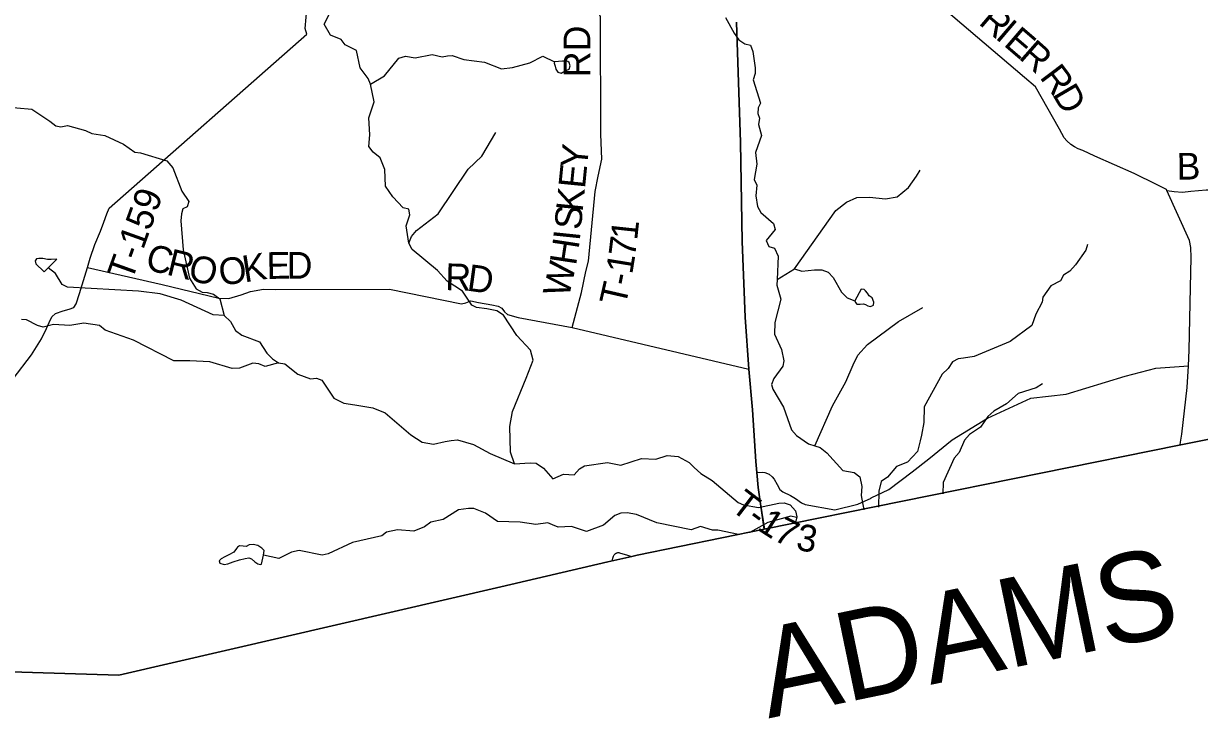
# Model space of a CAD drawing. Extents: x 1525783 to 1900577, y 218250 to 627376.
# Drawn here: x 1651566 to 1664775, y 372547 to 380350 of the extents above; entities that cross this region are included whole.
import ezdxf

# ---------------------------------------------------------------- set-up
doc = ezdxf.new("R2010")
doc.units = 0
for name, color, linetype in [('GM_X_Adjacent_County', 7, 'Continuous'), ('GM_X_Adjacent_County_Text', 7, 'Continuous'), ('GM_X_County', 7, 'Continuous'), ('GM_X_County_Road', 7, 'Continuous'), ('GM_X_Minor_Lake', 7, 'Continuous'), ('GM_X_Minor_River', 7, 'Continuous'), ('GM_X_State_Route', 7, 'Continuous'), ('GM_X_Township', 7, 'Continuous'), ('GM_X_Township_Road', 7, 'Continuous'), ('GM_X_Township_Road_Text', 7, 'Continuous'), ('GM_X_Township_ROW', 7, 'Continuous')]:
    doc.layers.add(name, color=color, linetype=linetype)

msp = doc.modelspace()

# ---------------------------------------------------------------- linework, layer by layer
at = {"layer": 'GM_X_Adjacent_County'}
msp.add_lwpolyline([(1639218, 373602), (1647962, 373191), (1648875, 373148), (1652636, 373033), (1656929, 374027), (1658129, 374305), (1658400, 374367), (1658458, 374381), (1659887, 374671), (1664545, 375615), (1665666, 375842), (1669148, 376597), (1674179, 377598), (1676204, 378017), (1679810, 378742), (1683755, 379513), (1684465, 379654), (1684870, 379728), (1687556, 380216)], dxfattribs=at)
at = {"layer": 'GM_X_County'}
msp.add_lwpolyline([(1687556, 380216), (1684870, 379728), (1684465, 379654), (1683755, 379513), (1679810, 378742), (1676204, 378017), (1674179, 377598), (1669148, 376597), (1665666, 375842), (1664545, 375615), (1659887, 374671), (1658458, 374381), (1658400, 374367), (1658129, 374305), (1656929, 374027), (1652636, 373033), (1648875, 373148), (1647962, 373191), (1639218, 373602)], dxfattribs=at)
at = {"layer": 'GM_X_County_Road'}
msp.add_lwpolyline([(1658176, 374315), (1658181, 374330), (1658186, 374347), (1658190, 374360), (1658194, 374370), (1658198, 374377), (1658201, 374383), (1658206, 374388), (1658209, 374392), (1658213, 374396), (1658218, 374400), (1658221, 374402), (1658226, 374404), (1658231, 374406), (1658236, 374408), (1658241, 374409), (1658247, 374410), (1658253, 374409), (1658261, 374408), (1658271, 374405), (1658287, 374400), (1658350, 374380), (1658394, 374366)], dxfattribs=at)
at = {"layer": 'GM_X_Minor_Lake'}
for points in [[(1657532, 379919), (1657528, 379905), (1657537, 379871), (1657547, 379837), (1657569, 379802), (1657607, 379794), (1657651, 379819), (1657694, 379837), (1657706, 379873), (1657696, 379913), (1657681, 379925), (1657646, 379926), (1657620, 379926)], [(1657620, 379926), (1657532, 379919)], [(1651940, 377704), (1651878, 377701), (1651837, 377699), (1651785, 377710), (1651737, 377713), (1651711, 377707), (1651697, 377685), (1651706, 377653), (1651732, 377627), (1651768, 377592), (1651800, 377560), (1651842, 377607)], [(1651842, 377607), (1651940, 377704)], [(1660904, 377238), (1660912, 377217), (1660928, 377197), (1660964, 377199), (1661000, 377204), (1661024, 377196), (1661050, 377180), (1661080, 377171), (1661114, 377187), (1661117, 377223), (1661097, 377269), (1661064, 377294), (1661046, 377322), (1661024, 377350), (1661008, 377363), (1660976, 377369)], [(1660976, 377369), (1660904, 377238)], [(1654263, 374382), (1654270, 374432), (1654242, 374461), (1654200, 374491), (1654146, 374500), (1654102, 374496), (1654068, 374479), (1654034, 374483), (1653994, 374484), (1653969, 374470), (1653959, 374456), (1653927, 374416), (1653874, 374383), (1653828, 374361), (1653787, 374340), (1653765, 374318), (1653771, 374290), (1653819, 374277), (1653863, 374285), (1653923, 374306), (1653994, 374327), (1654056, 374343), (1654098, 374350), (1654128, 374340), (1654166, 374305), (1654200, 374283), (1654224, 374276), (1654238, 374280)], [(1654238, 374280), (1654263, 374382)]]:
    msp.add_lwpolyline(points, dxfattribs=at)
at = {"layer": 'GM_X_Minor_River'}
for points in [[(1655894, 377882), (1655863, 378077), (1655904, 378201), (1655895, 378265), (1655831, 378282), (1655714, 378402), (1655631, 378523), (1655625, 378709), (1655573, 378840), (1655493, 378904), (1655444, 378968), (1655456, 379100), (1655444, 379291), (1655506, 379469), (1655462, 379670), (1655439, 379732), (1655346, 379851), (1655307, 380048), (1655181, 380112), (1655135, 380169), (1655016, 380220), (1654943, 380342), (1655013, 380481)], [(1659452, 380417), (1659548, 380241), (1659601, 380168), (1659667, 380123), (1659731, 380106), (1659760, 380036), (1659786, 379853), (1659785, 379787), (1659763, 379717), (1659844, 379456), (1659817, 379404), (1659814, 379338), (1659834, 379287), (1659823, 379217), (1659855, 379093), (1659789, 378903), (1659803, 378771), (1659775, 378598), (1659803, 378536), (1659793, 378416), (1659810, 378295), (1659849, 378229), (1659990, 378105), (1660009, 378036), (1659909, 377915), (1659937, 377845), (1660001, 377826), (1660044, 377739), (1660031, 377477), (1660028, 377411), (1660072, 377256), (1660007, 376992), (1660003, 376862), (1660081, 376690), (1660106, 376564), (1660095, 376502), (1659995, 376365), (1659968, 376295), (1659982, 376243), (1660102, 376041), (1660191, 375789), (1660250, 375726), (1660384, 375632), (1660453, 375607), (1660513, 375589), (1660589, 375530), (1660769, 375331), (1660897, 375309), (1660961, 375260), (1660984, 375152), (1660974, 375050), (1661005, 374888)], [(1655462, 379670), (1655620, 379762), (1655781, 379960), (1655857, 379982), (1655966, 379966), (1656155, 380000), (1656269, 379976), (1656329, 379986), (1656381, 379989), (1656511, 379947), (1656743, 379915), (1656937, 379842), (1657058, 379855), (1657253, 379910), (1657398, 379985)], [(1657398, 379985), (1657532, 379919)], [(1651152, 379434), (1651661, 379388), (1651862, 379255), (1651928, 379202), (1651984, 379189), (1652060, 379204), (1652262, 379150), (1652332, 379115), (1652478, 379091), (1652688, 378996), (1652815, 378904), (1652879, 378897), (1653177, 378808), (1653242, 378731), (1653345, 378467), (1653424, 378352), (1653405, 378292), (1653355, 378268), (1653340, 378212), (1653333, 378136), (1653358, 377807), (1653432, 377492), (1653505, 377370), (1653573, 377335), (1653631, 377329), (1653701, 377312), (1653770, 377259), (1653820, 377072), (1653890, 377005), (1653949, 376902), (1654018, 376851), (1654218, 376776), (1654299, 376647), (1654362, 376584), (1654432, 376541), (1654500, 376530), (1654649, 376414), (1654791, 376362), (1654859, 376367), (1654917, 376347), (1655053, 376143), (1655165, 376087), (1655289, 376068), (1655489, 376035), (1655627, 375979), (1655915, 375733), (1656044, 375651), (1656170, 375628), (1656301, 375656), (1656369, 375669), (1656440, 375677), (1656622, 375624), (1656807, 375522), (1657080, 375406), (1657259, 375416), (1657325, 375415), (1657407, 375356), (1657510, 375238), (1657631, 375289), (1657753, 375284), (1657810, 375349), (1657869, 375382), (1658126, 375421), (1658202, 375406), (1658276, 375393), (1658508, 375467), (1658668, 375457), (1658795, 375499), (1658919, 375488), (1659043, 375420), (1659100, 375365), (1659174, 375296), (1659301, 375219), (1659595, 374972), (1659655, 374946), (1659821, 374917), (1660050, 374965), (1660111, 374970), (1660179, 374945), (1660236, 374880), (1660251, 374810), (1660233, 374732)], [(1657080, 375406), (1657038, 375537), (1657029, 375824), (1657057, 375992), (1657214, 376369), (1657289, 376570), (1657262, 376681), (1657106, 376847), (1656958, 377077), (1656882, 377124), (1656772, 377148), (1656656, 377163), (1656602, 377188), (1656498, 377346), (1656325, 377456), (1656216, 377576), (1655930, 377814), (1655894, 377882), (1655925, 377958), (1655982, 378026), (1656225, 378213), (1656561, 378716), (1656713, 378859), (1656870, 379127)], [(1660031, 377477), (1660227, 377595), (1660690, 378251), (1660809, 378345), (1660928, 378396), (1661067, 378400), (1661247, 378380), (1661378, 378402), (1661508, 378509), (1661597, 378636), (1661636, 378704)], [(1663518, 377869), (1663499, 377805), (1663381, 377640), (1663318, 377571), (1663247, 377524), (1663214, 377460), (1663105, 377403), (1663015, 377276), (1663009, 377222), (1662937, 377088), (1662893, 376961), (1662650, 376781), (1662243, 376612), (1662126, 376591), (1662064, 376584), (1662000, 376551), (1661953, 376475), (1661886, 376412), (1661681, 376045), (1661678, 375869), (1661651, 375729), (1661638, 375665), (1661606, 375545), (1661495, 375424), (1661372, 375376), (1661270, 375257), (1661201, 375207), (1661174, 375099), (1661169, 374921)], [(1653820, 377072), (1653696, 377079), (1653337, 377244), (1653101, 377313), (1652858, 377346), (1652062, 377390), (1651999, 377421), (1651924, 377544), (1651842, 377607)], [(1660227, 377595), (1660307, 377568), (1660451, 377586), (1660535, 377583), (1660605, 377558), (1660661, 377499), (1660753, 377332), (1660819, 377269), (1660904, 377238)], [(1660453, 375607), (1660653, 376058), (1660803, 376327), (1660884, 376516), (1660939, 376626), (1661045, 376747), (1661395, 377005), (1661668, 377162)], [(1654432, 376541), (1654281, 376499), (1654209, 376530), (1654141, 376535), (1653994, 376480), (1653909, 376477), (1653661, 376551), (1653435, 376563), (1653254, 376564), (1652800, 376794), (1652484, 376906), (1652418, 376961), (1652244, 376987), (1652087, 376959), (1651903, 376971), (1651788, 376942), (1651722, 376959), (1651601, 377023), (1651544, 377027)], [(1663010, 376304), (1662941, 376258), (1662738, 376197), (1662608, 376080), (1662464, 375998), (1662399, 375936), (1662314, 375817), (1662190, 375734), (1662134, 375673), (1662076, 375535), (1662021, 375470), (1661897, 375197), (1661894, 375068)], [(1660250, 374803), (1660185, 374817), (1659925, 374746), (1659723, 374634), (1659599, 374613), (1659365, 374662), (1659306, 374661), (1659171, 374701), (1659066, 374666), (1658680, 374745), (1658452, 374838), (1658348, 374857), (1658274, 374852), (1658209, 374825), (1658079, 374718), (1657890, 374646), (1657720, 374703), (1657573, 374696), (1657508, 374723), (1657454, 374742), (1657321, 374724), (1657143, 374752), (1656892, 374759), (1656755, 374853), (1656623, 374905), (1656563, 374905), (1656454, 374891), (1656280, 374782), (1656142, 374750), (1656069, 374697), (1655950, 374650), (1655767, 374666), (1655645, 374638), (1655590, 374598), (1655262, 374524), (1654988, 374397), (1654921, 374380), (1654661, 374433), (1654575, 374414), (1654433, 374342), (1654263, 374382)]]:
    msp.add_lwpolyline(points, dxfattribs=at)
at = {"layer": 'GM_X_State_Route'}
msp.add_lwpolyline([(1659894, 374673), (1659817, 375140), (1659803, 375310), (1659792, 375433), (1659754, 376014), (1659712, 376469), (1659671, 377052), (1659637, 377902), (1659618, 379014), (1659575, 380363)], dxfattribs=at)
at = {"layer": 'GM_X_Township'}
for points in [[(1659575, 380363), (1659618, 379014), (1659637, 377902), (1659671, 377052), (1659712, 376469), (1659754, 376014), (1659792, 375433), (1659803, 375310), (1659817, 375140), (1659887, 374671), (1658458, 374381), (1658400, 374367), (1658129, 374305), (1656929, 374027), (1652636, 373033), (1648875, 373148)], [(1665666, 375842), (1664545, 375615), (1659887, 374671), (1659817, 375140), (1659803, 375310), (1659792, 375433), (1659754, 376014), (1659712, 376469), (1659671, 377052), (1659637, 377902), (1659618, 379014), (1659575, 380363)]]:
    msp.add_lwpolyline(points, dxfattribs=at)
at = {"layer": 'GM_X_Township_Road'}
for points in [[(1657729, 376935), (1657832, 377331), (1657884, 377564), (1657911, 377680), (1657988, 378465), (1658020, 378637), (1658063, 378828), (1658050, 379109), (1658046, 380425), (1657891, 380808), (1657400, 381768), (1657344, 382030), (1657320, 382261), (1657307, 382385), (1657271, 382480), (1657218, 382602), (1657225, 383900)], [(1664559, 375618), (1664562, 375649), (1664578, 375739), (1664635, 376263), (1664650, 376505), (1664661, 376681), (1664674, 377386), (1664680, 377724), (1664679, 377836), (1664663, 377915), (1664410, 378476), (1664405, 378488), (1664292, 378541), (1664040, 378664), (1663601, 378859), (1663464, 378924), (1663412, 378941), (1663373, 378964), (1663329, 378990), (1663286, 379031), (1663257, 379067), (1663204, 379165), (1662935, 379638), (1662811, 379744), (1661830, 380579)], [(1664410, 378476), (1664492, 378464), (1664584, 378458), (1664678, 378466), (1664849, 378481), (1664886, 378483), (1664886, 378483)], [(1652285, 377612), (1652315, 377717), (1652366, 377870), (1652430, 378020), (1652467, 378118), (1652503, 378212)], [(1651450, 376361), (1651657, 376631), (1651770, 376810), (1651825, 376927), (1651854, 376994), (1651886, 377056), (1651927, 377095), (1652010, 377123), (1652080, 377141), (1652131, 377160), (1652158, 377201), (1652195, 377319), (1652285, 377612), (1653122, 377420), (1653759, 377266), (1653872, 377264), (1654011, 377304), (1654116, 377340), (1654261, 377366), (1654399, 377363), (1655676, 377366), (1656485, 377202), (1656534, 377212), (1656592, 377235), (1656678, 377219), (1656825, 377191), (1656899, 377175), (1656939, 377154), (1656970, 377114), (1657001, 377081), (1657124, 377048), (1657729, 376935), (1659712, 376469)], [(1659803, 375310), (1659863, 375313), (1659894, 375309), (1659940, 375290), (1659974, 375260), (1659999, 375235), (1660033, 375173), (1660063, 375119), (1660095, 375091), (1660182, 375049), (1660238, 375017), (1660305, 374969), (1660346, 374950), (1660678, 374889), (1660939, 374952), (1661086, 375022), (1661088, 375023)]]:
    msp.add_lwpolyline(points, dxfattribs=at)
at = {"layer": 'GM_X_Township_ROW'}
for points in [[(1652503, 378212), (1652529, 378278), (1654748, 380229), (1654730, 380294), (1654753, 380550), (1654718, 380669), (1654721, 380686)], [(1661088, 375023), (1661286, 375118), (1661547, 375315), (1661734, 375463), (1661999, 375675), (1662393, 375919), (1662881, 376144), (1663279, 376189), (1663942, 376389), (1664284, 376479), (1664650, 376505)]]:
    msp.add_lwpolyline(points, dxfattribs=at)

# ---------------------------------------------------------------- texts
at = {"layer": 'GM_X_Adjacent_County_Text'}
msp.add_text('ADAMS COUNTY', height=1000, rotation=11.713, dxfattribs=at).set_placement((1659934, 372547))
at = {"layer": 'GM_X_Township_Road_Text'}
for s, rotation, p in [('R', 319.4409, (1662284, 380350)), ('RD', 90, (1657933, 379747)), ('I', 319.4368, (1662471, 380189)), ('E', 319.4378, (1662565, 380109)), ('R', 318.5376, (1662734, 379964)), ('R', 306.962, (1662972, 379746)), ('D', 300.354, (1663115, 379557)), ('Y', 84.3087, (1657894, 378713)), ('B', 0.3083, (1664519, 378597)), ('E', 84.3077, (1657872, 378490)), ('T-159', 70.2343, (1652782, 377445)), ('K', 84.3096, (1657846, 378227)), ('S', 84.3078, (1657826, 378026)), ('1', 83.8568, (1658458, 377909)), ('H', 81.3816, (1657772, 377626)), ('I', 84.0952, (1657813, 377902)), ('7', 82.9361, (1658434, 377720)), ('C', 346.3031, (1652923, 377591)), ('R', 346.3031, (1653162, 377533)), ('K', 9.0067, (1654049, 377442)), ('E', 0.66, (1654298, 377482)), ('D', 0.0073, (1654522, 377485)), ('O', 346.4104, (1653402, 377474)), ('O', 7.5426, (1653779, 377406)), ('R', 358.6651, (1656301, 377357)), ('D', 352.1692, (1656538, 377352)), ('W', 77.1522, (1657690, 377263)), ('1', 80.8065, (1658403, 377526)), ('-', 78.6818, (1658377, 377393)), ('T', 77.0833, (1658325, 377165)), ('T', 322.5464, (1659493, 374899)), ('1', 327.3086, (1659793, 374674)), ('-', 323.6513, (1659677, 374759)), ('7', 332.7209, (1659975, 374559)), ('3', 350.147, (1660233, 374443))]:
    msp.add_text(s, height=300, rotation=rotation, dxfattribs=at).set_placement(p)

doc.saveas('drawing.dxf')
